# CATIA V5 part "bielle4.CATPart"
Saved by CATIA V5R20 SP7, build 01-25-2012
Part number: bielle4
Publications: "droite_bielle_4", "droite_pivot_4_5", "droite_pivot_4_2"
Bounding box of the stored display mesh (mm): x 0 to 0.5, y 1.52 to 1.52, z 1.4 to 2.4
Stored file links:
  U:\IAO\bielle4.CATPart
  U:\IAO\skl_brevet_iao.CATProduct
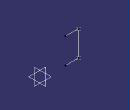
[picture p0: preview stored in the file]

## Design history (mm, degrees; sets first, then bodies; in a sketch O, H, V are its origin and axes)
Set1
  Point1 "point E": linked copy from another document
  Point2 "point F": linked copy from another document
Set2
  Line1 "droite_bielle_4": type PtPt, FirstPoint Point1, SecondPoint Point2
  Line2 "droite_pivot_4_5": type Normal, RefPoint Point2, RefSkin yz-plane, Start 0, End 0.5
  Line3 "droite_pivot_4_2": type Normal, RefPoint Point1, RefSkin yz-plane, Start 0, End 0.5
Body1 (main body)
